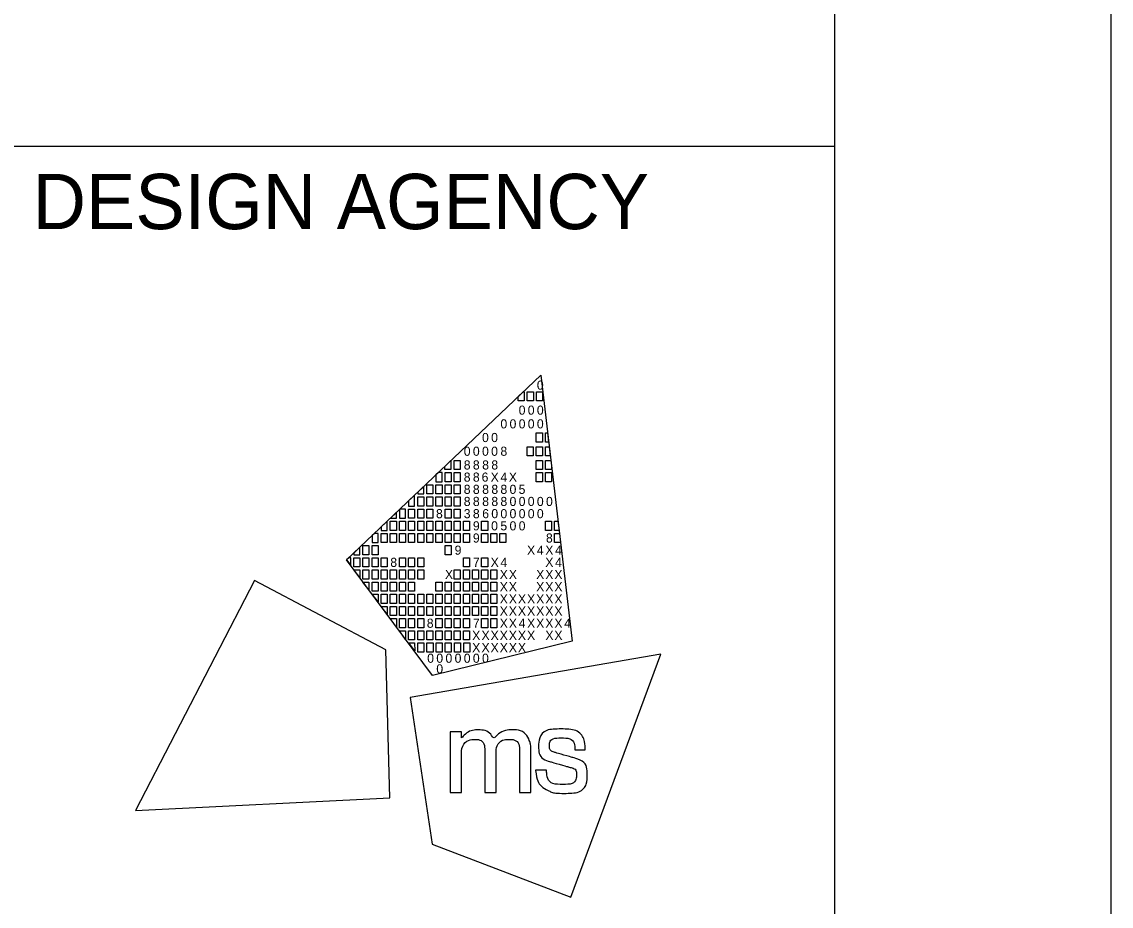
# Model space of a CAD drawing. Extents: x 0 to 52.3, y 0 to 22.
# Drawn here: x 32.03 to 34, y 3.126 to 4.725 of the extents above; entities that cross this region are included whole.
import ezdxf

# ---------------------------------------------------------------- set-up
doc = ezdxf.new("R2010")
doc.units = 0
for name, color, linetype in [('SH_Border', 7, 'Continuous'), ('SH_Cut_Line', 7, 'Continuous'), ('SH_Data', 7, 'Continuous')]:
    doc.layers.add(name, color=color, linetype=linetype)

msp = doc.modelspace()

# ---------------------------------------------------------------- linework, layer by layer
at = {"layer": 'SH_Border'}
for p, q in [((32, 4.5), (33.5, 4.5)), ((32.6175, 3.7519), (32.9688, 4.0861)), ((32.9688, 4.0861), (32.9688, 4.0861)), ((32.9688, 4.0861), (33.0253, 3.6052)), ((32.773, 3.543), (32.6175, 3.7519)), ((33.0253, 3.6052), (32.773, 3.543))]:
    msp.add_line(p, q, dxfattribs=at)
for points in [[(1.5, 21.5), (33.5, 21.5), (33.5, 0.5), (1.5, 0.5)], [(32.9279, 4.0472), (32.9369, 4.0558), (32.9389, 4.0558), (32.9389, 4.0393), (32.9279, 4.0393)], [(32.9444, 4.0558), (32.9554, 4.0558), (32.9554, 4.0393), (32.9444, 4.0393)], [(32.9609, 4.0558), (32.9719, 4.0558), (32.9719, 4.0393), (32.9609, 4.0393)], [(32.9606, 3.9815), (32.9716, 3.9815), (32.9716, 3.965), (32.9606, 3.965)], [(32.9771, 3.9815), (32.9811, 3.9815), (32.983, 3.965), (32.9771, 3.965)], [(32.9441, 3.9567), (32.9551, 3.9567), (32.9551, 3.9402), (32.9441, 3.9402)], [(32.9606, 3.9567), (32.9716, 3.9567), (32.9716, 3.9402), (32.9606, 3.9402)], [(32.9771, 3.9567), (32.984, 3.9567), (32.9859, 3.9402), (32.9771, 3.9402)], [(32.7953, 3.9211), (32.8064, 3.9316), (32.8064, 3.9154), (32.7953, 3.9154)], [(32.8123, 3.9319), (32.8233, 3.9319), (32.8233, 3.9154), (32.8123, 3.9154)], [(32.9606, 3.9319), (32.9716, 3.9319), (32.9716, 3.9154), (32.9606, 3.9154)], [(32.9771, 3.9319), (32.9869, 3.9319), (32.9881, 3.9218), (32.9881, 3.9154), (32.9771, 3.9154)], [(32.7958, 3.9099), (32.8068, 3.9099), (32.8068, 3.8934), (32.7958, 3.8934)], [(32.8123, 3.9099), (32.8233, 3.9099), (32.8233, 3.8934), (32.8123, 3.8934)], [(32.9606, 3.9099), (32.9716, 3.9099), (32.9716, 3.8934), (32.9606, 3.8934)], [(32.9771, 3.9099), (32.9881, 3.9099), (32.9881, 3.8934), (32.9771, 3.8934)], [(32.7627, 3.8879), (32.7737, 3.8879), (32.7737, 3.8714), (32.7627, 3.8714)], [(32.7793, 3.8879), (32.7903, 3.8879), (32.7903, 3.8714), (32.7793, 3.8714)], [(32.7958, 3.8879), (32.8068, 3.8879), (32.8068, 3.8714), (32.7958, 3.8714)], [(32.8123, 3.8879), (32.8233, 3.8879), (32.8233, 3.8714), (32.8123, 3.8714)], [(32.7462, 3.8659), (32.7572, 3.8659), (32.7572, 3.8494), (32.7462, 3.8494)], [(32.7627, 3.8659), (32.7737, 3.8659), (32.7737, 3.8494), (32.7627, 3.8494)], [(32.7793, 3.8659), (32.7903, 3.8659), (32.7903, 3.8494), (32.7793, 3.8494)], [(32.7958, 3.8659), (32.8068, 3.8659), (32.8068, 3.8494), (32.7958, 3.8494)], [(32.8123, 3.8659), (32.8233, 3.8659), (32.8233, 3.8494), (32.8123, 3.8494)], [(32.7297, 3.8439), (32.7407, 3.8439), (32.7407, 3.8273), (32.7297, 3.8273)], [(32.7462, 3.8439), (32.7572, 3.8439), (32.7572, 3.8273), (32.7462, 3.8273)], [(32.7627, 3.8439), (32.7737, 3.8439), (32.7737, 3.8273), (32.7627, 3.8273)], [(32.7958, 3.8439), (32.8068, 3.8439), (32.8068, 3.8273), (32.7958, 3.8273)], [(32.8123, 3.8439), (32.8233, 3.8439), (32.8233, 3.8273), (32.8123, 3.8273)], [(32.6967, 3.8218), (32.7077, 3.8218), (32.7077, 3.8053), (32.6967, 3.8053)], [(32.7132, 3.8218), (32.7242, 3.8218), (32.7242, 3.8053), (32.7132, 3.8053)], [(32.7297, 3.8218), (32.7407, 3.8218), (32.7407, 3.8053), (32.7297, 3.8053)], [(32.7462, 3.8218), (32.7572, 3.8218), (32.7572, 3.8053), (32.7462, 3.8053)], [(32.7627, 3.8218), (32.7737, 3.8218), (32.7737, 3.8053), (32.7627, 3.8053)], [(32.7793, 3.8218), (32.7903, 3.8218), (32.7903, 3.8053), (32.7793, 3.8053)], [(32.7958, 3.8218), (32.8068, 3.8218), (32.8068, 3.8053), (32.7958, 3.8053)], [(32.8123, 3.8218), (32.8233, 3.8218), (32.8233, 3.8053), (32.8123, 3.8053)], [(32.8288, 3.8218), (32.8398, 3.8218), (32.8398, 3.8053), (32.8288, 3.8053)], [(32.8618, 3.8218), (32.8728, 3.8218), (32.8728, 3.8053), (32.8618, 3.8053)], [(32.9771, 3.8218), (32.9881, 3.8218), (32.9881, 3.8053), (32.9771, 3.8053)], [(32.9935, 3.8218), (32.9998, 3.8218), (33.0018, 3.8053), (32.9935, 3.8053)], [(32.6802, 3.7998), (32.6912, 3.7998), (32.6912, 3.7833), (32.6802, 3.7833)], [(32.6967, 3.7998), (32.7077, 3.7998), (32.7077, 3.7833), (32.6967, 3.7833)], [(32.7132, 3.7998), (32.7242, 3.7998), (32.7242, 3.7833), (32.7132, 3.7833)], [(32.7297, 3.7998), (32.7407, 3.7998), (32.7407, 3.7833), (32.7297, 3.7833)], [(32.7462, 3.7998), (32.7572, 3.7998), (32.7572, 3.7833), (32.7462, 3.7833)], [(32.7627, 3.7998), (32.7737, 3.7998), (32.7737, 3.7833), (32.7627, 3.7833)], [(32.7793, 3.7998), (32.7903, 3.7998), (32.7903, 3.7833), (32.7793, 3.7833)], [(32.7958, 3.7998), (32.8068, 3.7998), (32.8068, 3.7833), (32.7958, 3.7833)], [(32.8123, 3.7998), (32.8233, 3.7998), (32.8233, 3.7833), (32.8123, 3.7833)], [(32.8288, 3.7998), (32.8398, 3.7998), (32.8398, 3.7833), (32.8288, 3.7833)], [(32.8618, 3.7998), (32.8728, 3.7998), (32.8728, 3.7833), (32.8618, 3.7833)], [(32.8783, 3.7998), (32.8893, 3.7998), (32.8893, 3.7833), (32.8783, 3.7833)], [(32.8947, 3.7998), (32.9057, 3.7998), (32.9057, 3.7833), (32.8947, 3.7833)], [(32.9935, 3.7998), (33.0024, 3.7998), (33.0044, 3.7833), (32.9935, 3.7833)], [(32.6471, 3.7778), (32.6581, 3.7778), (32.6581, 3.7613), (32.6471, 3.7613)], [(32.6637, 3.7778), (32.6747, 3.7778), (32.6747, 3.7613), (32.6637, 3.7613)], [(32.7958, 3.7778), (32.8068, 3.7778), (32.8068, 3.7613), (32.7958, 3.7613)], [(32.6306, 3.7558), (32.6416, 3.7558), (32.6416, 3.7393), (32.6306, 3.7393)], [(32.6471, 3.7558), (32.6581, 3.7558), (32.6581, 3.7393), (32.6471, 3.7393)], [(32.6637, 3.7558), (32.6747, 3.7558), (32.6747, 3.7393), (32.6637, 3.7393)], [(32.6802, 3.7558), (32.6912, 3.7558), (32.6912, 3.7393), (32.6802, 3.7393)], [(32.7132, 3.7558), (32.7242, 3.7558), (32.7242, 3.7393), (32.7132, 3.7393)], [(32.7297, 3.7558), (32.7407, 3.7558), (32.7407, 3.7393), (32.7297, 3.7393)], [(32.7462, 3.7558), (32.7572, 3.7558), (32.7572, 3.7393), (32.7462, 3.7393)], [(32.8288, 3.7558), (32.8398, 3.7558), (32.8398, 3.7393), (32.8288, 3.7393)], [(32.8618, 3.7558), (32.8728, 3.7558), (32.8728, 3.7393), (32.8618, 3.7393)], [(32.6306, 3.7338), (32.6416, 3.7338), (32.6416, 3.72)], [(32.6471, 3.7338), (32.6581, 3.7338), (32.6581, 3.7173), (32.6471, 3.7173)], [(32.6637, 3.7338), (32.6747, 3.7338), (32.6747, 3.7173), (32.6637, 3.7173)], [(32.6802, 3.7338), (32.6912, 3.7338), (32.6912, 3.7173), (32.6802, 3.7173)], [(32.6967, 3.7338), (32.7077, 3.7338), (32.7077, 3.7173), (32.6967, 3.7173)], [(32.7132, 3.7338), (32.7242, 3.7338), (32.7242, 3.7173), (32.7132, 3.7173)], [(32.7297, 3.7338), (32.7407, 3.7338), (32.7407, 3.7173), (32.7297, 3.7173)], [(32.7462, 3.7338), (32.7572, 3.7338), (32.7572, 3.7173), (32.7462, 3.7173)], [(32.8123, 3.7338), (32.8233, 3.7338), (32.8233, 3.7173), (32.8123, 3.7173)], [(32.8288, 3.7338), (32.8398, 3.7338), (32.8398, 3.7173), (32.8288, 3.7173)], [(32.8453, 3.7338), (32.8563, 3.7338), (32.8563, 3.7173), (32.8453, 3.7173)], [(32.8618, 3.7338), (32.8728, 3.7338), (32.8728, 3.7173), (32.8618, 3.7173)], [(32.8783, 3.7338), (32.8893, 3.7338), (32.8893, 3.7173), (32.8783, 3.7173)], [(32.6471, 3.7117), (32.6581, 3.7117), (32.6581, 3.698)], [(32.6637, 3.7117), (32.6747, 3.7117), (32.6747, 3.6952), (32.6637, 3.6952)], [(32.6802, 3.7117), (32.6912, 3.7117), (32.6912, 3.6952), (32.6802, 3.6952)], [(32.6967, 3.7117), (32.7077, 3.7117), (32.7077, 3.6952), (32.6967, 3.6952)], [(32.7132, 3.7117), (32.7242, 3.7117), (32.7242, 3.6952), (32.7132, 3.6952)], [(32.7297, 3.7117), (32.7407, 3.7117), (32.7407, 3.6952), (32.7297, 3.6952)], [(32.7793, 3.7117), (32.7903, 3.7117), (32.7903, 3.6952), (32.7793, 3.6952)], [(32.7958, 3.7117), (32.8068, 3.7117), (32.8068, 3.6952), (32.7958, 3.6952)], [(32.8123, 3.7117), (32.8233, 3.7117), (32.8233, 3.6952), (32.8123, 3.6952)], [(32.8288, 3.7117), (32.8398, 3.7117), (32.8398, 3.6952), (32.8288, 3.6952)], [(32.8453, 3.7117), (32.8563, 3.7117), (32.8563, 3.6952), (32.8453, 3.6952)], [(32.8618, 3.7117), (32.8728, 3.7117), (32.8728, 3.6952), (32.8618, 3.6952)], [(32.8783, 3.7117), (32.8893, 3.7117), (32.8893, 3.6952), (32.8783, 3.6952)], [(32.6637, 3.6897), (32.6747, 3.6897), (32.6747, 3.676)], [(32.6747, 3.6897), (32.6747, 3.6897), (32.6747, 3.6897)], [(32.6802, 3.6897), (32.6912, 3.6897), (32.6912, 3.6732), (32.6802, 3.6732)], [(32.6967, 3.6897), (32.7077, 3.6897), (32.7077, 3.6732), (32.6967, 3.6732)], [(32.7132, 3.6897), (32.7242, 3.6897), (32.7242, 3.6732), (32.7132, 3.6732)], [(32.7297, 3.6897), (32.7407, 3.6897), (32.7407, 3.6732), (32.7297, 3.6732)], [(32.7462, 3.6897), (32.7572, 3.6897), (32.7572, 3.6732), (32.7462, 3.6732)], [(32.7627, 3.6897), (32.7737, 3.6897), (32.7737, 3.6732), (32.7627, 3.6732)], [(32.7793, 3.6897), (32.7903, 3.6897), (32.7903, 3.6732), (32.7793, 3.6732)], [(32.7958, 3.6897), (32.8068, 3.6897), (32.8068, 3.6732), (32.7958, 3.6732)], [(32.8123, 3.6897), (32.8233, 3.6897), (32.8233, 3.6732), (32.8123, 3.6732)], [(32.8288, 3.6897), (32.8398, 3.6897), (32.8398, 3.6732), (32.8288, 3.6732)], [(32.8453, 3.6897), (32.8563, 3.6897), (32.8563, 3.6732), (32.8453, 3.6732)], [(32.8618, 3.6897), (32.8728, 3.6897), (32.8728, 3.6732), (32.8618, 3.6732)], [(32.8783, 3.6897), (32.8893, 3.6897), (32.8893, 3.6732), (32.8783, 3.6732)], [(32.6802, 3.6677), (32.6912, 3.6677), (32.6912, 3.654)], [(32.6967, 3.6677), (32.7077, 3.6677), (32.7077, 3.6512), (32.6967, 3.6512)], [(32.7132, 3.6677), (32.7242, 3.6677), (32.7242, 3.6512), (32.7132, 3.6512)], [(32.7297, 3.6677), (32.7407, 3.6677), (32.7407, 3.6512), (32.7297, 3.6512)], [(32.7462, 3.6677), (32.7572, 3.6677), (32.7572, 3.6512), (32.7462, 3.6512)], [(32.7627, 3.6677), (32.7737, 3.6677), (32.7737, 3.6512), (32.7627, 3.6512)], [(32.7793, 3.6677), (32.7903, 3.6677), (32.7903, 3.6512), (32.7793, 3.6512)], [(32.7958, 3.6677), (32.8068, 3.6677), (32.8068, 3.6512), (32.7958, 3.6512)], [(32.8123, 3.6677), (32.8233, 3.6677), (32.8233, 3.6512), (32.8123, 3.6512)], [(32.8288, 3.6677), (32.8398, 3.6677), (32.8398, 3.6512), (32.8288, 3.6512)], [(32.8453, 3.6677), (32.8563, 3.6677), (32.8563, 3.6512), (32.8453, 3.6512)], [(32.8618, 3.6677), (32.8728, 3.6677), (32.8728, 3.6512), (32.8618, 3.6512)], [(32.8783, 3.6677), (32.8893, 3.6677), (32.8893, 3.6512), (32.8783, 3.6512)], [(32.7077, 3.6305), (32.6965, 3.6457), (32.7077, 3.6457)], [(32.7132, 3.6457), (32.7242, 3.6457), (32.7242, 3.6292), (32.7132, 3.6292)], [(32.7297, 3.6457), (32.7407, 3.6457), (32.7407, 3.6292), (32.7297, 3.6292)], [(32.7462, 3.6457), (32.7572, 3.6457), (32.7572, 3.6292), (32.7462, 3.6292)], [(32.7793, 3.6457), (32.7903, 3.6457), (32.7903, 3.6292), (32.7793, 3.6292)], [(32.7958, 3.6457), (32.8068, 3.6457), (32.8068, 3.6292), (32.7958, 3.6292)], [(32.8123, 3.6457), (32.8233, 3.6457), (32.8233, 3.6292), (32.8123, 3.6292)], [(32.8288, 3.6457), (32.8398, 3.6457), (32.8398, 3.6292), (32.8288, 3.6292)], [(32.8618, 3.6457), (32.8728, 3.6457), (32.8728, 3.6292), (32.8618, 3.6292)], [(32.8783, 3.6457), (32.8893, 3.6457), (32.8893, 3.6292), (32.8783, 3.6292)], [(32.724, 3.6082), (32.7132, 3.6237), (32.7242, 3.6237)], [(32.7297, 3.6237), (32.7407, 3.6237), (32.7407, 3.6072), (32.7297, 3.6072)], [(32.7462, 3.6237), (32.7572, 3.6237), (32.7572, 3.6072), (32.7462, 3.6072)], [(32.7627, 3.6237), (32.7737, 3.6237), (32.7737, 3.6072), (32.7627, 3.6072)], [(32.7793, 3.6237), (32.7903, 3.6237), (32.7903, 3.6072), (32.7793, 3.6072)], [(32.7958, 3.6237), (32.8068, 3.6237), (32.8068, 3.6072), (32.7958, 3.6072)], [(32.8123, 3.6237), (32.8233, 3.6237), (32.8233, 3.6072), (32.8123, 3.6072)], [(32.8288, 3.6237), (32.8398, 3.6237), (32.8398, 3.6072), (32.8288, 3.6072)], [(32.7302, 3.6017), (32.7407, 3.6017), (32.7408, 3.5875)], [(32.7463, 3.6017), (32.7573, 3.6017), (32.7573, 3.5852), (32.7463, 3.5852)], [(32.763, 3.6017), (32.774, 3.6017), (32.774, 3.5852), (32.763, 3.5852)], [(32.7794, 3.6017), (32.7904, 3.6017), (32.7904, 3.5852), (32.7794, 3.5852)], [(32.796, 3.6017), (32.807, 3.6017), (32.807, 3.5852), (32.796, 3.5852)], [(32.8129, 3.6017), (32.8239, 3.6017), (32.8239, 3.5851), (32.8129, 3.5851)], [(32.8296, 3.6017), (32.8406, 3.6017), (32.8406, 3.5851), (32.8296, 3.5851)]]:
    msp.add_lwpolyline(points, close=True, dxfattribs=at)
for points in [[(32.7903, 3.9099), (32.7836, 3.9099), (32.7793, 3.9058), (32.7793, 3.8934), (32.7903, 3.8934), (32.7903, 3.9099)], [(32.7572, 3.8849), (32.7462, 3.8744), (32.7462, 3.8714), (32.7572, 3.8714), (32.7572, 3.8849)], [(32.7407, 3.8691), (32.7297, 3.8587), (32.7297, 3.8494), (32.7407, 3.8494), (32.7407, 3.8691)], [(32.7242, 3.8439), (32.7141, 3.8439), (32.7132, 3.843), (32.7132, 3.8273), (32.7242, 3.8273), (32.7242, 3.8439)], [(32.6912, 3.822), (32.6802, 3.8115), (32.6802, 3.8053), (32.6912, 3.8053), (32.6912, 3.822)], [(32.7077, 3.8377), (32.6968, 3.8273), (32.7077, 3.8273), (32.7077, 3.8377)], [(32.6747, 3.7998), (32.6679, 3.7998), (32.6637, 3.7958), (32.6637, 3.7833), (32.6747, 3.7833), (32.6747, 3.7998)], [(32.6416, 3.7749), (32.6306, 3.7644), (32.6306, 3.7613), (32.6416, 3.7613), (32.6416, 3.7749)], [(32.6251, 3.7558), (32.6216, 3.7558), (32.6175, 3.7519), (32.6251, 3.7417), (32.6251, 3.7558)], [(32.4512, 3.7149), (32.2359, 3.2988), (32.6956, 3.3215), (32.6884, 3.5892), (32.4512, 3.7149)], [(33.0229, 3.1422), (33.1859, 3.5814), (32.7324, 3.5029), (32.7722, 3.2381), (33.0229, 3.1422)]]:
    msp.add_lwpolyline(points, dxfattribs=at)
for points in [[(32.8048, 3.3315), (32.8048, 3.3315), (32.8048, 3.4409), (32.8048, 3.4409), (32.8048, 3.4409), (32.8255, 3.4409), (32.8255, 3.4409), (32.8255, 3.4409), (32.8255, 3.4297), (32.8255, 3.4297), (32.8346, 3.4399), (32.8457, 3.4445), (32.8555, 3.4445), (32.8688, 3.4445), (32.8791, 3.4372), (32.8837, 3.4266), (32.8915, 3.4381), (32.905, 3.4446), (32.9166, 3.4446), (32.9325, 3.4446), (32.9451, 3.435), (32.9494, 3.4213), (32.9494, 3.4212), (32.9494, 3.4212), (32.9494, 3.4212), (32.9501, 3.419), (32.9506, 3.4172), (32.9506, 3.4071), (32.9506, 3.4071), (32.9506, 3.3314), (32.9506, 3.3314), (32.9506, 3.3314), (32.9303, 3.3314), (32.9303, 3.3314), (32.9303, 3.3314), (32.9303, 3.4048), (32.9303, 3.4048), (32.9303, 3.4201), (32.9219, 3.4274), (32.911, 3.4274), (32.8995, 3.4274), (32.8879, 3.4171), (32.8879, 3.4001), (32.8879, 3.4001), (32.8879, 3.3315), (32.8879, 3.3315), (32.8879, 3.3315), (32.8674, 3.3315), (32.8674, 3.3315), (32.8674, 3.3315), (32.8674, 3.4059), (32.8674, 3.4059), (32.8674, 3.4203), (32.8588, 3.4274), (32.8496, 3.4274), (32.8384, 3.4274), (32.8254, 3.417), (32.8254, 3.3962), (32.8254, 3.3962), (32.8254, 3.3315), (32.8254, 3.3315), (32.8254, 3.3315), (32.8048, 3.3315), (32.8048, 3.3315)], [(32.9595, 3.3709), (32.9595, 3.3709), (32.9595, 3.3717), (32.9595, 3.3717), (32.9595, 3.3717), (32.9603, 3.3717), (32.9603, 3.3717), (32.9603, 3.3717), (32.9783, 3.3717), (32.9783, 3.3717), (32.9783, 3.3717), (32.9789, 3.3717), (32.9789, 3.3717), (32.9789, 3.3717), (32.979, 3.371), (32.979, 3.371), (32.9803, 3.3554), (32.9887, 3.346), (33.009, 3.346), (33.0273, 3.346), (33.0333, 3.3554), (33.0333, 3.3631), (33.0333, 3.3732), (33.0256, 3.3758), (33.0175, 3.378), (33.0175, 3.378), (32.987, 3.3867), (32.987, 3.3867), (32.972, 3.3909), (32.9648, 3.4019), (32.9648, 3.4142), (32.9648, 3.4303), (32.9768, 3.4462), (33.0052, 3.4462), (33.0348, 3.4462), (33.0489, 3.4285), (33.0489, 3.4095), (33.0489, 3.4095), (33.0489, 3.4087), (33.0489, 3.4087), (33.0489, 3.4087), (33.0482, 3.4087), (33.0482, 3.4087), (33.0482, 3.4087), (33.0312, 3.4087), (33.0312, 3.4087), (33.0312, 3.4087), (33.0305, 3.4087), (33.0305, 3.4087), (33.0305, 3.4087), (33.0305, 3.4094), (33.0305, 3.4094), (33.0301, 3.4208), (33.0226, 3.43), (33.0056, 3.43), (32.9891, 3.43), (32.9843, 3.4218), (32.9843, 3.4157), (32.9843, 3.4108), (32.9869, 3.4059), (32.9959, 3.4033), (32.9959, 3.4033), (33.0255, 3.3948), (33.0255, 3.3948), (33.0462, 3.3889), (33.0527, 3.3777), (33.0527, 3.3639), (33.0527, 3.3462), (33.041, 3.3298), (33.0087, 3.3298), (32.9952, 3.3298), (32.9877, 3.3321), (32.9823, 3.3348), (32.969, 3.3414), (32.9609, 3.3536), (32.9595, 3.3709)]]:
    msp.add_open_spline(points, degree=3, dxfattribs=at)
at = {"layer": 'SH_Cut_Line'}
msp.add_lwpolyline([(0, 0), (34, 0), (34, 22), (0, 22)], close=True, dxfattribs=at)
at = {"layer": 'SH_Data'}
msp.add_line((32.75, 3.5), (32.75, 3.5), dxfattribs=at)

# ---------------------------------------------------------------- texts
at = {"layer": 'SH_Border'}
for s, p in [('0', (32.9617, 4.0597)), ('0', (32.9288, 4.0145)), ('0', (32.9452, 4.0145)), ('0', (32.9617, 4.0145)), ('0', (32.8958, 3.9897)), ('0', (32.9123, 3.9897)), ('0', (32.9288, 3.9897)), ('0', (32.9452, 3.9897)), ('0', (32.9617, 3.9897)), ('0', (32.8625, 3.965)), ('0', (32.879, 3.965)), ('0', (32.8295, 3.9402)), ('0', (32.846, 3.9402)), ('0', (32.8625, 3.9402)), ('0', (32.879, 3.9402)), ('8', (32.8958, 3.9402)), ('8', (32.8295, 3.9154)), ('8', (32.846, 3.9154)), ('8', (32.8628, 3.9154)), ('8', (32.8793, 3.9154)), ('8', (32.8295, 3.8934)), ('8', (32.846, 3.8934)), ('6', (32.8618, 3.8934)), ('X', (32.8781, 3.8934)), ('4', (32.8958, 3.8934)), ('X', (32.911, 3.8934)), ('8', (32.8295, 3.8713)), ('8', (32.846, 3.8713)), ('8', (32.8628, 3.8713)), ('8', (32.8794, 3.8713)), ('8', (32.8958, 3.8713)), ('0', (32.9123, 3.8713)), ('5', (32.9287, 3.8713)), ('8', (32.8295, 3.8494)), ('8', (32.846, 3.8494)), ('8', (32.8628, 3.8494)), ('8', (32.8794, 3.8494)), ('8', (32.8958, 3.8494)), ('0', (32.9123, 3.8494)), ('0', (32.9288, 3.8494)), ('0', (32.9452, 3.8494)), ('0', (32.9617, 3.8494)), ('0', (32.9782, 3.8494)), ('8', (32.7793, 3.8273)), ('3', (32.8295, 3.8273)), ('8', (32.846, 3.8273)), ('6', (32.8629, 3.8273)), ('0', (32.8793, 3.8273)), ('0', (32.8958, 3.8273)), ('0', (32.9123, 3.8273)), ('0', (32.9288, 3.8273)), ('0', (32.9452, 3.8273)), ('0', (32.9617, 3.8273)), ('9', (32.846, 3.8053)), ('0', (32.879, 3.8053)), ('5', (32.8957, 3.8053)), ('0', (32.9123, 3.8053)), ('0', (32.9288, 3.8053)), ('9', (32.846, 3.7833)), ('8', (32.9781, 3.7833)), ('9', (32.813, 3.7613)), ('X', (32.9439, 3.7613)), ('4', (32.9617, 3.7613)), ('X', (32.9769, 3.7613)), ('4', (32.9946, 3.7613)), ('8', (32.6967, 3.7393)), ('7', (32.846, 3.7393)), ('X', (32.8781, 3.7393)), ('4', (32.8958, 3.7393)), ('X', (32.9769, 3.7393)), ('4', (32.9946, 3.7393)), ('X', (32.7955, 3.7173)), ('X', (32.8945, 3.7173)), ('X', (32.911, 3.7173)), ('X', (32.9604, 3.7173)), ('X', (32.9769, 3.7173)), ('X', (32.9933, 3.7173)), ('X', (32.8945, 3.6952)), ('X', (32.911, 3.6952)), ('X', (32.9604, 3.6952)), ('X', (32.9769, 3.6952)), ('X', (32.9933, 3.6952)), ('X', (32.8945, 3.6732)), ('X', (32.911, 3.6732)), ('X', (32.9274, 3.6732)), ('X', (32.9439, 3.6732)), ('X', (32.9604, 3.6732)), ('X', (32.9769, 3.6732)), ('X', (32.9933, 3.6732)), ('X', (32.8945, 3.6512)), ('X', (32.911, 3.6512)), ('X', (32.9274, 3.6512)), ('X', (32.9439, 3.6512)), ('X', (32.9604, 3.6512)), ('X', (32.9769, 3.6512)), ('X', (32.9933, 3.6512)), ('8', (32.7627, 3.6292)), ('7', (32.846, 3.6292)), ('X', (32.8945, 3.6292)), ('X', (32.911, 3.6292)), ('4', (32.9288, 3.6292)), ('X', (32.9439, 3.6292)), ('X', (32.9604, 3.6292)), ('X', (32.9769, 3.6292)), ('X', (32.9933, 3.6292)), ('4', (33.0111, 3.6292)), ('X', (32.8447, 3.6072)), ('X', (32.8616, 3.6072)), ('X', (32.878, 3.6072)), ('X', (32.8945, 3.6072)), ('X', (32.911, 3.6072)), ('X', (32.9274, 3.6072)), ('X', (32.9439, 3.6072)), ('X', (32.9771, 3.6072)), ('X', (32.9933, 3.6072)), ('X', (32.8447, 3.5851)), ('X', (32.8616, 3.5851)), ('X', (32.878, 3.5851)), ('X', (32.8945, 3.5851)), ('X', (32.911, 3.5851)), ('X', (32.9274, 3.5851)), ('0', (32.7634, 3.5659)), ('0', (32.7799, 3.5659)), ('0', (32.7965, 3.5659)), ('0', (32.813, 3.5659)), ('0', (32.8295, 3.5659)), ('0', (32.846, 3.5659)), ('0', (32.8625, 3.5659)), ('0', (32.7799, 3.5467))]:
    msp.add_text(s, height=0.0165, rotation=360, dxfattribs=at).set_placement(p)
at = {"layer": 'SH_Data'}
msp.add_text('DESIGN AGENCY', height=0.1, dxfattribs=at).set_placement((32.05, 4.35))

doc.saveas('drawing.dxf')
